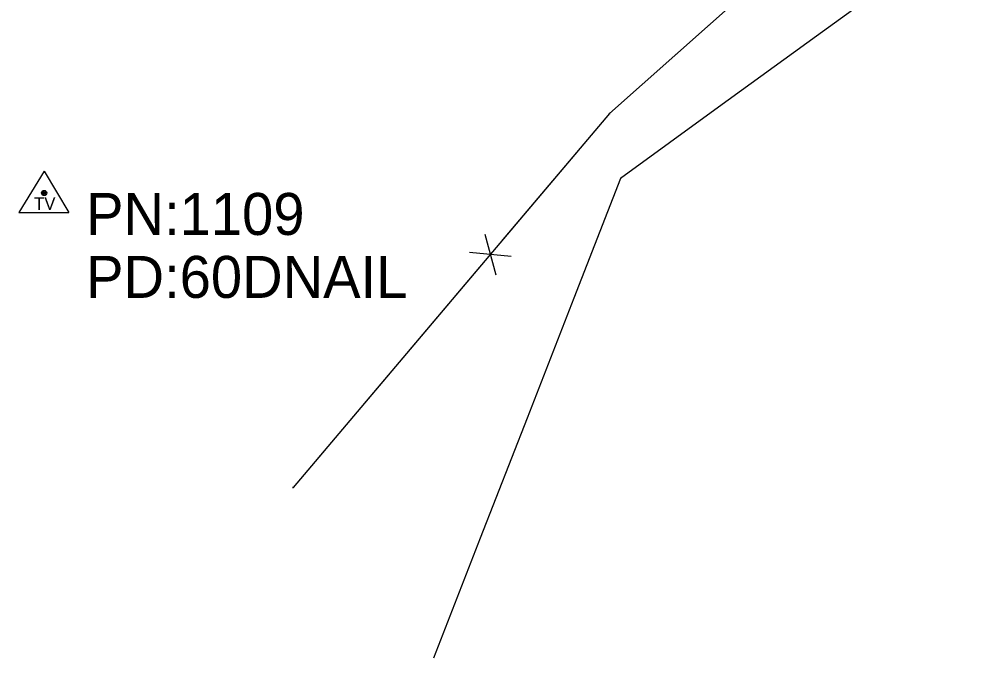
# Model space of a CAD drawing. Extents: x 1050807 to 1053552, y 395828 to 398415.
# Drawn here: x 1052141.6 to 1052254, y 396391.8 to 396468 of the extents above; entities that cross this region are included whole.
import ezdxf

# ---------------------------------------------------------------- set-up
doc = ezdxf.new("R2010")
doc.units = 0
for name, color, linetype in [('S_DITCHLINE', 7, 'Continuous'), ('S_FENCE', 7, 'Continuous'), ('S_MSC_PT_SYM', 7, 'Continuous'), ('S_SECONDARY_CTL', 7, 'Continuous'), ('S_SECONDARY_CTL_ANNOT', 7, 'Continuous')]:
    doc.layers.add(name, color=color, linetype=linetype)

msp = doc.modelspace()

# ---------------------------------------------------------------- linework, layer by layer
at = {"layer": 'S_DITCHLINE'}
msp.add_lwpolyline([(1052248.31, 396474.43), (1052236.63, 396465.95), (1052224.94, 396457.47), (1052213.26, 396449), (1052207.7, 396434.71), (1052202.13, 396420.42), (1052196.56, 396406.13), (1052191, 396391.84)], dxfattribs=at)
at = {"layer": 'S_FENCE'}
for p, q in [((1052253.96, 396494.07), (1052211.97, 396456.73)), ((1052211.97, 396456.73), (1052174.25, 396412.17)), ((1052197.12, 396442.36), (1052198.4, 396437.52)), ((1052197.12, 396442.36), (1052198.4, 396437.52)), ((1052200.25, 396439.71), (1052195.27, 396440.17)), ((1052200.25, 396439.71), (1052195.27, 396440.17))]:
    msp.add_line(p, q, dxfattribs=at)
for points in [[(1052236.03, 396478.12), (1052211.97, 396456.73)], [(1052236.03, 396478.12), (1052211.97, 396456.73)], [(1052211.97, 396456.73), (1052199.05, 396441.47)], [(1052211.97, 396456.73), (1052199.05, 396441.47)], [(1052196.47, 396438.41), (1052174.25, 396412.17)], [(1052196.47, 396438.41), (1052174.25, 396412.17)]]:
    msp.add_lwpolyline(points, dxfattribs=at)
at = {"layer": 'S_MSC_PT_SYM'}
for points in [[(1052211.97, 396456.73), (1052211.97, 396456.78), (1052211.97, 396456.73), (1052211.92, 396456.73), (1052211.97, 396456.73), (1052211.97, 396456.68), (1052211.97, 396456.73), (1052212.02, 396456.73)], [(1052174.25, 396412.17), (1052174.25, 396412.22), (1052174.25, 396412.17), (1052174.2, 396412.17), (1052174.25, 396412.17), (1052174.25, 396412.12), (1052174.25, 396412.17), (1052174.3, 396412.17)]]:
    msp.add_lwpolyline(points, dxfattribs=at)
at = {"layer": 'S_SECONDARY_CTL'}
for p, q in [((1052144.6, 396449.87), (1052141.59, 396444.92)), ((1052144.6, 396449.87), (1052147.55, 396444.92)), ((1052141.59, 396444.92), (1052147.55, 396444.92))]:
    msp.add_line(p, q, dxfattribs=at)
for radius in [0.311, 0.183, 0.103]:
    msp.add_circle((1052144.6, 396447.26), radius, dxfattribs=at)

# ---------------------------------------------------------------- texts
msp.add_text('TV', height=1.5, dxfattribs=at).set_placement((1052143.39, 396445.25))
at = {"layer": 'S_SECONDARY_CTL_ANNOT'}
for s, p in [('PN:1109', (1052149.6, 396442.26)), ('PD:60DNAIL', (1052149.6, 396434.76))]:
    msp.add_text(s, height=5, dxfattribs=at).set_placement(p)

doc.saveas('drawing.dxf')
